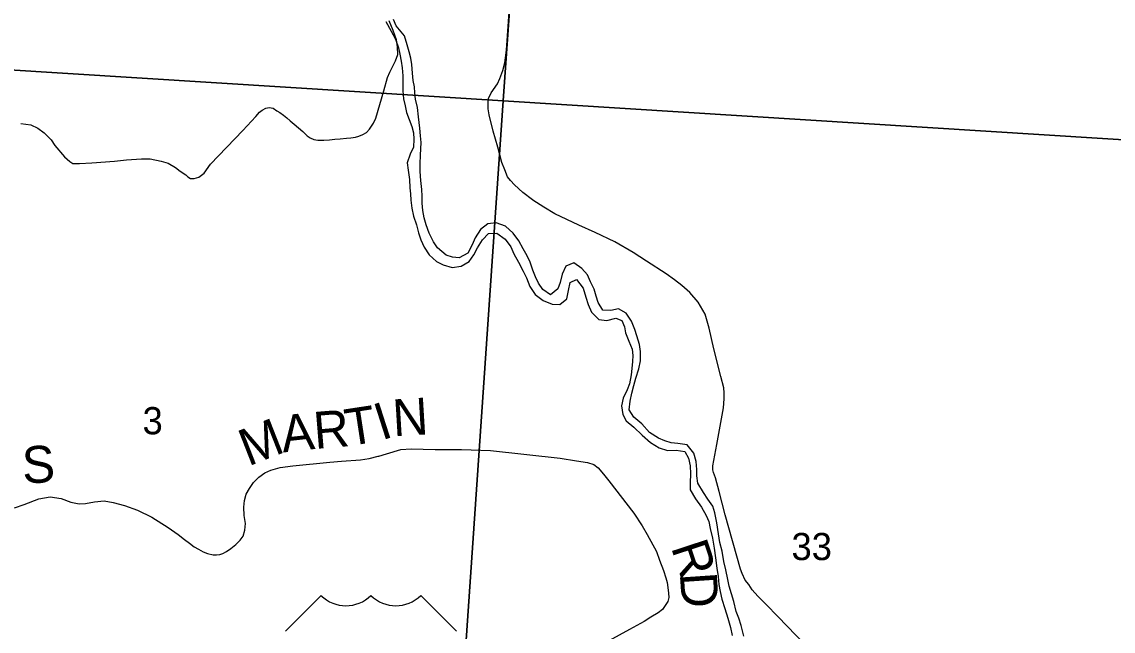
# Model space of a CAD drawing. Extents: x 0 to 34, y 0 to 22.
# Drawn here: x 3.724 to 5.404, y 17.932 to 18.871 of the extents above; entities that cross this region are included whole.
import ezdxf

# ---------------------------------------------------------------- set-up
doc = ezdxf.new("R2010")
doc.units = 0
for name, color, linetype in [('GM_X_Corporation', 7, 'Continuous'), ('GM_X_County_Road', 7, 'Continuous'), ('GM_X_County_Road_Text', 7, 'Continuous'), ('GM_X_Major_River', 7, 'Continuous'), ('GM_X_Section_Text', 7, 'Continuous'), ('GM_X_State_Route', 7, 'Continuous'), ('GM_X_Township_Road', 7, 'Continuous'), ('GM_X_US_Shield', 7, 'Continuous')]:
    doc.layers.add(name, color=color, linetype=linetype)

msp = doc.modelspace()

# ---------------------------------------------------------------- linework, layer by layer
at = {"layer": 'GM_X_Corporation'}
for points in [[(3.5308, 19.8461), (4.5379, 19.7849), (4.465, 18.749), (3.459, 18.812), (3.474, 19.0276), (3.5026, 19.4408)], [(4.5379, 19.7849), (5.5693, 19.7272), (5.5363, 19.3151), (5.5032, 18.9017), (5.4857, 18.6848), (4.465, 18.749)], [(4.465, 18.749), (4.3947, 17.724), (3.3856, 17.7912), (3.4438, 18.6342), (3.459, 18.812)], [(5.4857, 18.6848), (5.4744, 18.5035), (5.4208, 17.6557), (4.3947, 17.724), (4.465, 18.749)]]:
    msp.add_lwpolyline(points, close=True, dxfattribs=at)
at = {"layer": 'GM_X_County_Road'}
for points in [[(3.7127, 18.1223), (3.7277, 18.1276), (3.7502, 18.1362), (3.7674, 18.1395), (3.7844, 18.137), (3.7993, 18.1313), (3.8124, 18.1286), (3.822, 18.129), (3.8356, 18.1315), (3.8505, 18.1331), (3.8648, 18.1307), (3.8822, 18.1258), (3.9023, 18.1186), (3.9242, 18.1082), (3.9492, 18.092), (3.9645, 18.0813), (3.9744, 18.0738), (3.9822, 18.0678), (3.9893, 18.0625), (3.9959, 18.0586), (4.003, 18.0545), (4.0098, 18.052), (4.0184, 18.05), (4.0237, 18.05), (4.0286, 18.0506), (4.0333, 18.0523), (4.0391, 18.0553), (4.046, 18.0596), (4.0536, 18.066), (4.0603, 18.0727), (4.0645, 18.0789), (4.0673, 18.0881), (4.0681, 18.0983), (4.0665, 18.1108), (4.0659, 18.1233), (4.067, 18.1337), (4.0696, 18.1432), (4.0743, 18.152), (4.0808, 18.1616), (4.0888, 18.1698), (4.098, 18.1765), (4.1072, 18.1804), (4.1218, 18.1845), (4.141, 18.187), (4.1984, 18.1927), (4.2164, 18.1941), (4.2452, 18.1964), (4.2586, 18.1984), (4.2725, 18.2017), (4.2734, 18.202)], [(4.2734, 18.202), (4.2856, 18.2056), (4.3077, 18.212), (4.3232, 18.213), (4.3605, 18.2122), (4.401, 18.212), (4.4457, 18.2107), (4.5528, 18.1988), (4.5782, 18.1945), (4.5947, 18.1923), (4.6046, 18.189), (4.6111, 18.1841), (4.6197, 18.1741), (4.6279, 18.1638), (4.6664, 18.1141), (4.6791, 18.0946), (4.6869, 18.0813), (4.7012, 18.0553), (4.7057, 18.042), (4.7121, 18.026), (4.7157, 18.0146), (4.7176, 18.0072), (4.7186, 17.9996), (4.7194, 17.991), (4.72, 17.9841), (4.7184, 17.9783), (4.7147, 17.9718), (4.7102, 17.9656), (4.7035, 17.9609), (4.6922, 17.9538), (4.682, 17.9472), (4.6598, 17.9349), (4.6119, 17.9087)]]:
    msp.add_lwpolyline(points, dxfattribs=at)
at = {"layer": 'GM_X_Major_River'}
for points in [[(4.2844, 18.8713), (4.2928, 18.8561), (4.2992, 18.844), (4.3038, 18.8307), (4.306, 18.8208), (4.3079, 18.8102), (4.3095, 18.7999), (4.3106, 18.7874), (4.3106, 18.7642), (4.3117, 18.7521), (4.314, 18.7415), (4.3163, 18.7312)], [(4.3348, 18.7243), (4.333, 18.7388), (4.3303, 18.7517), (4.3292, 18.7612), (4.3284, 18.7707), (4.3265, 18.7806), (4.3254, 18.7919), (4.3246, 18.8049), (4.3227, 18.8147), (4.3201, 18.8246), (4.3174, 18.8352), (4.3129, 18.8493), (4.3004, 18.8645), (4.2962, 18.8744)], [(4.3163, 18.7312), (4.3243, 18.7095), (4.327, 18.6996), (4.3273, 18.6901), (4.3269, 18.6776), (4.322, 18.667), (4.317, 18.6537), (4.3189, 18.6423), (4.3208, 18.6279), (4.3215, 18.6153), (4.3223, 18.6059), (4.323, 18.596), (4.3246, 18.5838), (4.3268, 18.5713), (4.3317, 18.558), (4.3348, 18.5459), (4.3382, 18.5349), (4.3435, 18.5239), (4.3511, 18.5121), (4.3624, 18.5018), (4.3727, 18.4965), (4.3867, 18.4923), (4.4004, 18.4946), (4.4126, 18.5018), (4.4198, 18.512), (4.4255, 18.5227), (4.4331, 18.5348), (4.4426, 18.5447), (4.4555, 18.5454), (4.468, 18.5363), (4.4771, 18.5242), (4.4817, 18.5135), (4.4889, 18.5006), (4.4957, 18.4869), (4.501, 18.4767), (4.5063, 18.4634), (4.5143, 18.4509), (4.5264, 18.4414), (4.5405, 18.4361), (4.5522, 18.4357), (4.5629, 18.444), (4.5659, 18.4569), (4.5682, 18.4691), (4.5781, 18.474), (4.588, 18.4607), (4.5925, 18.447), (4.5959, 18.4356), (4.6012, 18.4235), (4.6122, 18.4125), (4.6247, 18.4106), (4.6384, 18.4144), (4.6479, 18.4109), (4.6521, 18.4011), (4.6532, 18.3916), (4.6585, 18.3791), (4.6638, 18.3669), (4.6649, 18.357), (4.6642, 18.3475), (4.6634, 18.3369), (4.6619, 18.3271), (4.6596, 18.3134), (4.6561, 18.3039), (4.6497, 18.291), (4.6474, 18.2796), (4.6493, 18.266), (4.6546, 18.2565), (4.666, 18.2466), (4.6789, 18.2344), (4.6921, 18.223), (4.7054, 18.2147), (4.7183, 18.2109), (4.7312, 18.2113), (4.7449, 18.209), (4.7506, 18.1987), (4.7529, 18.1873), (4.7536, 18.1748), (4.7528, 18.1608), (4.7528, 18.1501), (4.7612, 18.1361), (4.7703, 18.1232), (4.7778, 18.1106), (4.7816, 18.1012), (4.7839, 18.0905), (4.7873, 18.0757), (4.7899, 18.0602), (4.7918, 18.0454), (4.7941, 18.0294), (4.796, 18.0169), (4.7971, 18.0044), (4.799, 17.9937), (4.802, 17.982), (4.8066, 17.9672), (4.8111, 17.9527), (4.8149, 17.9379), (4.8179, 17.9258)], [(4.8358, 17.925), (4.8316, 17.941), (4.8278, 17.9527), (4.8236, 17.963), (4.8202, 17.9782), (4.8165, 17.9899), (4.813, 18.0017), (4.8108, 18.012), (4.8078, 18.0271), (4.8047, 18.04), (4.8021, 18.0556), (4.7987, 18.0689), (4.7964, 18.0826), (4.7942, 18.0993), (4.7911, 18.1148), (4.7881, 18.1247), (4.7801, 18.1357), (4.7733, 18.1459), (4.7646, 18.1604), (4.7635, 18.1714), (4.7635, 18.1816), (4.762, 18.1938), (4.7586, 18.2063), (4.7483, 18.2196), (4.7339, 18.2215), (4.7237, 18.2226), (4.7138, 18.2253), (4.7043, 18.2299), (4.6903, 18.2386), (4.6785, 18.2515), (4.6664, 18.2618), (4.6592, 18.2735), (4.6607, 18.2868), (4.6634, 18.299), (4.666, 18.3107), (4.6695, 18.3221), (4.674, 18.3365), (4.6767, 18.3487), (4.6767, 18.3631), (4.6752, 18.3737), (4.671, 18.3874), (4.668, 18.3969), (4.6627, 18.4098), (4.6547, 18.4223), (4.6426, 18.4288), (4.6308, 18.4261), (4.6183, 18.4265), (4.6111, 18.4383), (4.6081, 18.4482), (4.605, 18.4592), (4.5997, 18.4706), (4.5948, 18.4812), (4.5861, 18.4911), (4.5739, 18.4998), (4.5614, 18.4945), (4.5557, 18.4824), (4.5527, 18.4691), (4.5492, 18.4596), (4.5382, 18.4505), (4.5261, 18.4585), (4.5196, 18.4683), (4.5147, 18.4782), (4.5109, 18.4885), (4.5067, 18.5006), (4.5022, 18.5105), (4.4961, 18.5211), (4.4893, 18.5336), (4.4806, 18.5454), (4.4688, 18.556), (4.4544, 18.5614), (4.4415, 18.5595), (4.4301, 18.5511), (4.4221, 18.5379), (4.4171, 18.5272), (4.4107, 18.5143), (4.3974, 18.5071), (4.3871, 18.5083), (4.3773, 18.5113), (4.364, 18.5227), (4.3579, 18.5322), (4.3511, 18.5451), (4.3466, 18.558), (4.3435, 18.569), (4.3416, 18.58), (4.3405, 18.5914), (4.3401, 18.6024), (4.3398, 18.6123), (4.3383, 18.6263), (4.3371, 18.6404), (4.3375, 18.6521), (4.3379, 18.6654), (4.3383, 18.6753), (4.3387, 18.6848), (4.338, 18.695), (4.3365, 18.7072), (4.3348, 18.7243)]]:
    msp.add_lwpolyline(points, dxfattribs=at)
at = {"layer": 'GM_X_State_Route'}
msp.add_lwpolyline([(4.9296, 17.912), (4.8885, 17.9544), (4.8697, 17.9738), (4.857, 17.9862), (4.8483, 17.996), (4.8434, 18.0041), (4.8377, 18.0111), (4.8329, 18.0214), (4.8303, 18.0279), (4.8067, 18.1115), (4.7974, 18.1475), (4.7919, 18.1688), (4.7891, 18.1768), (4.7879, 18.1811), (4.7881, 18.1869), (4.794, 18.2199), (4.8044, 18.2765), (4.8055, 18.2902), (4.8053, 18.2992), (4.8047, 18.3069), (4.8003, 18.3247), (4.7893, 18.3674), (4.7821, 18.3992), (4.776, 18.4206), (4.7651, 18.4388), (4.7527, 18.4538), (4.7402, 18.4648), (4.7291, 18.4734), (4.7161, 18.4826), (4.6857, 18.5024), (4.6652, 18.5153), (4.6372, 18.5317), (4.6067, 18.5463), (4.5817, 18.5578), (4.5632, 18.5663), (4.5446, 18.5753), (4.5277, 18.5851), (4.5107, 18.5962), (4.51, 18.5968), (4.4955, 18.608), (4.4827, 18.6197), (4.4761, 18.6262), (4.4716, 18.632), (4.4676, 18.6426), (4.4631, 18.6541), (4.4568, 18.6775), (4.4499, 18.7026), (4.4433, 18.7275), (4.4422, 18.7365), (4.4421, 18.7456), (4.4426, 18.7528), (4.4467, 18.7612), (4.4563, 18.7751), (4.4601, 18.7833), (4.4647, 18.7956), (4.4675, 18.8075), (4.4701, 18.8269), (4.4757, 18.9089)], dxfattribs=at)
at = {"layer": 'GM_X_Township_Road'}
msp.add_lwpolyline([(3.7225, 18.714), (3.7376, 18.7119), (3.7484, 18.7068), (3.7585, 18.6996), (3.7689, 18.6888), (3.7748, 18.6804), (3.7899, 18.663), (3.7981, 18.6556), (3.8026, 18.6524), (3.8125, 18.6524), (3.8318, 18.6535), (3.8665, 18.6562), (3.8852, 18.6584), (3.9082, 18.6596), (3.9218, 18.6596), (3.9385, 18.6562), (3.9495, 18.6529), (3.9605, 18.6463), (3.9679, 18.641), (3.9766, 18.6351), (3.9798, 18.6321), (3.9838, 18.6294), (3.9893, 18.6296), (3.9965, 18.6315), (4.0048, 18.6376), (4.0147, 18.6514), (4.0643, 18.7033), (4.0842, 18.7248), (4.0901, 18.7316), (4.0941, 18.7348), (4.0998, 18.7378), (4.1049, 18.7386), (4.1109, 18.7378), (4.1168, 18.7339), (4.1212, 18.731), (4.1267, 18.7272), (4.1322, 18.7227), (4.1371, 18.7183), (4.1432, 18.7132), (4.1566, 18.7016), (4.1632, 18.6952), (4.1678, 18.692), (4.1733, 18.6893), (4.1795, 18.6886), (4.1888, 18.6886), (4.1979, 18.6891), (4.2057, 18.6899), (4.2142, 18.6905), (4.2239, 18.6914), (4.2305, 18.692), (4.2377, 18.6933), (4.243, 18.6946), (4.2491, 18.6973), (4.2546, 18.7001), (4.2591, 18.7052), (4.2625, 18.71), (4.2652, 18.7149), (4.2692, 18.7223), (4.2813, 18.7646), (4.2871, 18.7848), (4.2908, 18.7932), (4.2993, 18.8106), (4.3027, 18.8203), (4.3025, 18.8324), (4.3006, 18.843), (4.2955, 18.8576), (4.2896, 18.8722)], dxfattribs=at)
at = {"layer": 'GM_X_US_Shield'}
for p, q in [((4.1846, 17.9874), (4.1297, 17.9325)), ((4.3933, 17.9325), (4.3384, 17.9874))]:
    msp.add_line(p, q, dxfattribs=at)
for centre in [(4.223, 18.0266), (4.2999, 18.0266)]:
    msp.add_arc(centre, 0.0549, 225.573, 314.427, dxfattribs=at)

# ---------------------------------------------------------------- texts
at = {"layer": 'GM_X_County_Road_Text'}
for s, rotation, p in [('I', 17.7957, (4.2778, 18.226)), ('N', 3.4082, (4.2963, 18.2324)), ('A', 6.3885, (4.1261, 18.2075)), ('R', 4.6457, (4.1753, 18.213)), ('T', 8.6933, (4.2262, 18.2173)), ('M', 21.3961, (4.0725, 18.1859)), ('S', 2.666, (3.7255, 18.1598)), ('R', 288.1708, (4.7232, 18.0619)), ('D', 273.8497, (4.737, 18.0213))]:
    msp.add_text(s, height=0.0568, rotation=rotation, dxfattribs=at).set_placement(p)
at = {"layer": 'GM_X_Section_Text'}
for s, height, p in [('3', 0.0419, (3.9098, 18.2356)), ('33', 0.04186, (4.909, 18.0419))]:
    msp.add_text(s, height=height, rotation=0, dxfattribs=at).set_placement(p)

doc.saveas('drawing.dxf')
